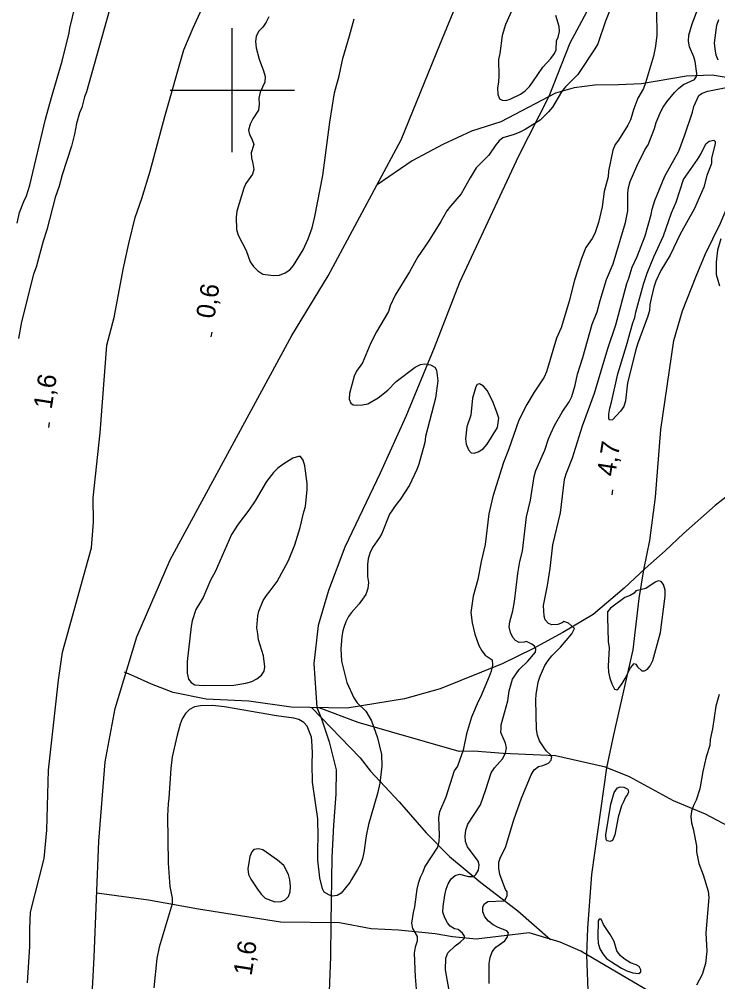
# Model space of a CAD drawing. Extents: x 282461 to 284471, y 5554090 to 5557646.
# Drawn here: x 282565.6 to 282678.3, y 5554656.3 to 5554811.4 of the extents above; entities that cross this region are included whole.
import ezdxf

# ---------------------------------------------------------------- set-up
doc = ezdxf.new("R2010")
doc.units = 0
for name, color, linetype in [('Niveau 1', 7, 'Continuous'), ('Niveau 2', 7, 'Continuous'), ('Niveau 22', 7, 'Continuous'), ('Niveau 3', 7, 'Continuous'), ('Niveau 4', 7, 'Continuous'), ('Niveau 61', 7, 'Continuous')]:
    doc.layers.add(name, color=color, linetype=linetype)

msp = doc.modelspace()

# ---------------------------------------------------------------- linework, layer by layer
at = {"layer": 'Niveau 1'}
for points in [[(282677.27, 5554788.31), (282677.22, 5554788.02), (282676.5, 5554786.22), (282676.01, 5554784.36), (282674.51, 5554780.92), (282672.21, 5554776.78), (282670.6, 5554773.4), (282669.08, 5554770.95), (282668.3, 5554769.2), (282667.97, 5554768.27), (282667.54, 5554766.41), (282667.33, 5554765.48), (282667.28, 5554764.5), (282667.01, 5554763.57), (282665.3, 5554759.09), (282665.03, 5554758.16), (282663.73, 5554752.82), (282663.38, 5554749.92), (282663.1, 5554749.05), (282662.6, 5554748.29), (282661.29, 5554746.88), (282660.83, 5554746.82), (282660.71, 5554747.1), (282660.7, 5554747.8), (282660.86, 5554748.78), (282661.13, 5554749.71), (282662.15, 5554754.3), (282663.57, 5554758.83), (282664.55, 5554762.49), (282664.88, 5554763.36), (282665.04, 5554764.23), (282666.29, 5554768.76), (282666.89, 5554770.51), (282667.95, 5554773.13), (282669.5, 5554776.5), (282670.83, 5554780.23), (282671.55, 5554781.97), (282672.76, 5554785.58), (282675.01, 5554788.85), (282675.51, 5554789.67), (282676.35, 5554791.36), (282676.86, 5554791.77), (282677.61, 5554791.96), (282677.85, 5554791.73), (282677.85, 5554791.33), (282677.26, 5554789.06), (282677.27, 5554788.31)], [(282660.51, 5554715.07), (282660.58, 5554711.14), (282660.77, 5554710.16), (282660.59, 5554707.21), (282660.66, 5554706.23), (282660.85, 5554705.25), (282661.16, 5554704.33), (282661.63, 5554703.47), (282661.98, 5554703.36), (282662.27, 5554703.6), (282662.83, 5554704.41), (282663.33, 5554705.23), (282664.17, 5554706.92), (282664.79, 5554707.62), (282665.08, 5554707.51), (282665.32, 5554707.11), (282666.03, 5554706.43), (282666.43, 5554706.44), (282666.94, 5554706.73), (282667.34, 5554707.26), (282667.79, 5554708.08), (282669.04, 5554712.61), (282669.8, 5554718.46), (282669.79, 5554719.44), (282669.54, 5554720.36), (282669.13, 5554720.82), (282668.66, 5554720.93), (282668.15, 5554720.74), (282666.67, 5554719.68), (282665.06, 5554719.31), (282664.77, 5554718.96), (282664.14, 5554718.6), (282663.28, 5554718.24), (282660.95, 5554716.52), (282660.5, 5554715.94), (282660.51, 5554715.07)], [(282663.04, 5554685.34), (282662.76, 5554684.7), (282662.22, 5554682.84), (282661.69, 5554680), (282661.3, 5554679.13), (282660.9, 5554678.95), (282660.38, 5554679.06), (282660.26, 5554679.34), (282660.24, 5554680.04), (282661.03, 5554684.96), (282661.57, 5554686.82), (282662.08, 5554687.58), (282662.54, 5554687.76), (282663.11, 5554687.71), (282663.75, 5554687.38), (282663.88, 5554686.97), (282663.71, 5554686.51), (282663.37, 5554686.1), (282663.04, 5554685.34)], [(282661.58, 5554662.83), (282660.92, 5554663.98), (282659.86, 5554665.58), (282659.44, 5554666.44), (282659.15, 5554666.44), (282658.98, 5554666.14), (282658.91, 5554663.54), (282658.98, 5554662.56), (282659.23, 5554661.64), (282659.71, 5554660.84), (282660.35, 5554660.1), (282661.11, 5554659.53), (282662.75, 5554658.52), (282663.62, 5554658.13), (282664.55, 5554657.79), (282665.53, 5554657.69), (282665.87, 5554657.93), (282665.87, 5554658.28), (282665.57, 5554658.79), (282665.1, 5554659.07), (282664.18, 5554659.41), (282663.36, 5554659.91), (282662.6, 5554660.54), (282662.01, 5554661.34), (282661.58, 5554662.83)]]:
    msp.add_lwpolyline(points, dxfattribs=at)
at = {"layer": 'Niveau 2'}
for points in [[(282673.61, 5554808.87), (282674.16, 5554810.68), (282675.82, 5554815.11)], [(282580.57, 5554814.3), (282576.48, 5554799.73), (282576.15, 5554798.91), (282575.72, 5554797.22), (282575.38, 5554796.35), (282574.89, 5554794.6), (282574.57, 5554792.91), (282574.09, 5554790.99), (282572.55, 5554786.33), (282572.06, 5554784.52), (282571.45, 5554782.71), (282570.09, 5554777.47), (282569.49, 5554775.67), (282568.35, 5554771.47), (282567.96, 5554770.36), (282566.01, 5554762.68), (282565.54, 5554760)], [(282578.7, 5554744.79), (282579.79, 5554758.9), (282580.93, 5554763.38), (282582.47, 5554771.35), (282583.33, 5554775.31), (282584.36, 5554779.5), (282585.4, 5554782.53), (282586.77, 5554786.96), (282589.11, 5554795.76), (282592.17, 5554806.48), (282593.67, 5554810.04), (282595.07, 5554813.08)], [(282661.24, 5554813.81), (282660.18, 5554811.12), (282658.91, 5554807.45), (282658.46, 5554806.63), (282655.7, 5554802.52), (282653.7, 5554800.52), (282653.08, 5554799.75), (282651.62, 5554797.23), (282650.99, 5554796.53), (282649.62, 5554795.17), (282647.22, 5554793.68), (282646.36, 5554793.21), (282645.44, 5554792.84), (282643.59, 5554792.29), (282643.02, 5554791.82), (282642.46, 5554791.17), (282641.33, 5554789.53), (282639.33, 5554787.46), (282638.32, 5554785.88), (282636.92, 5554783.31), (282635.15, 5554781.31), (282634.59, 5554780.54), (282633.63, 5554778.85), (282631.55, 5554775.56), (282629.91, 5554773.16), (282628.56, 5554770.7), (282626.25, 5554766.95), (282625.47, 5554765.26), (282625.2, 5554764.33), (282623.23, 5554761.05), (282622.33, 5554759.29), (282621, 5554756.08), (282620.04, 5554754.73)], [(282645.54, 5554813.89), (282644.02, 5554810.58), (282643.52, 5554808.78), (282643.15, 5554805.88), (282642.93, 5554804.95), (282642.97, 5554802.23), (282642.92, 5554801.31), (282642.76, 5554800.32), (282642.78, 5554799.34), (282643.07, 5554798.59), (282643.48, 5554798.36), (282644.12, 5554798.31), (282644.81, 5554798.54), (282646.47, 5554799.37), (282647.22, 5554799.9), (282647.9, 5554800.6), (282648.47, 5554801.35), (282650.06, 5554803.68), (282651.37, 5554805.08), (282651.94, 5554805.9), (282652.22, 5554806.48), (282652.26, 5554807.93)], [(282668.39, 5554812.72), (282668.45, 5554808.83), (282668.25, 5554807.09), (282667.88, 5554805.46), (282666.62, 5554801.15), (282666.29, 5554800.28), (282665.39, 5554798.7), (282664.72, 5554797.01), (282664.17, 5554795.2), (282663.78, 5554794.38), (282662.26, 5554791.92), (282661.7, 5554791.22), (282661.36, 5554790.34), (282660.67, 5554786.97), (282660.57, 5554786.04), (282659.97, 5554783.65), (282659.61, 5554781.21), (282659.02, 5554778.65), (282658.47, 5554776.91), (282658.02, 5554776.09), (282657, 5554774.62), (282656.28, 5554772.87), (282655.18, 5554769.38), (282654.32, 5554766), (282653.22, 5554762.39), (282653, 5554761.69), (282652.28, 5554760.06), (282650.63, 5554754.64), (282650.3, 5554753.77), (282648.66, 5554751.36), (282647.48, 5554749.37), (282646.2, 5554746.8), (282644.54, 5554742.02), (282643.71, 5554739.98), (282642.01, 5554734.51), (282641.36, 5554731.72), (282640.76, 5554726.78), (282640.11, 5554724.05), (282639.58, 5554721.14), (282638.82, 5554718.46), (282638.45, 5554715.85), (282638.66, 5554714.17), (282639.09, 5554712.33), (282639.76, 5554710.54), (282640.24, 5554709.68), (282640.77, 5554708.99), (282641.88, 5554708.2), (282641.96, 5554707.33), (282641.74, 5554706.4), (282641.41, 5554705.53), (282640.02, 5554702.2), (282639.63, 5554701.5), (282638.57, 5554698.99), (282637.75, 5554696.31), (282637.22, 5554693.64), (282636.28, 5554691.08), (282635.77, 5554690.31), (282634.4, 5554686.06), (282633.39, 5554683.73), (282633.24, 5554682.8), (282633.34, 5554679.91), (282633.3, 5554678.92), (282633.09, 5554678.05), (282631.06, 5554674.89), (282630.73, 5554674.01), (282630.28, 5554673.14), (282629.95, 5554672.2), (282629.73, 5554671.27), (282629.38, 5554668.43), (282629.16, 5554667.5), (282628.9, 5554665.76)], [(282652.26, 5554807.93), (282652.54, 5554808.51), (282652.76, 5554809.44), (282652.69, 5554810.25), (282652.15, 5554812.04)], [(282678.31, 5554804.85), (282678.01, 5554805.66), (282677.82, 5554806.64), (282677.74, 5554807.62), (282678.1, 5554810.46), (282678.43, 5554811.39)], [(282637.12, 5554664.16), (282636.42, 5554664.79), (282635.84, 5554664.89), (282635.14, 5554665.29), (282634.67, 5554665.86), (282634.25, 5554666.66), (282633.94, 5554667.58), (282633.99, 5554668.45), (282634.24, 5554670.31), (282634.46, 5554671.24), (282634.79, 5554672.11), (282635.3, 5554672.93), (282635.92, 5554673.46), (282636.61, 5554673.7), (282638.06, 5554673.32), (282638.93, 5554673.33), (282639.27, 5554673.63), (282639.67, 5554674.33), (282639.82, 5554675.2), (282639.64, 5554675.78), (282637.93, 5554678.07), (282637.62, 5554678.93), (282637.55, 5554679.8), (282637.65, 5554680.78), (282637.98, 5554681.71), (282640, 5554684.87), (282640.89, 5554687.32), (282641.71, 5554689.99), (282642.27, 5554690.81), (282643.58, 5554692.28), (282644.02, 5554693.16), (282644.18, 5554694.03), (282644.05, 5554694.78), (282643.27, 5554696.5), (282643.32, 5554697.2), (282643.37, 5554697.72), (282644.4, 5554701.61), (282644.66, 5554703.24), (282645.15, 5554705.1), (282646.22, 5554706.68), (282647.64, 5554707.98), (282648.89, 5554709.44), (282648.94, 5554709.91), (282648.7, 5554710.43), (282648.29, 5554710.71), (282647.42, 5554711.16), (282647.07, 5554711.04), (282646.26, 5554711.02), (282645.68, 5554711.3), (282645.21, 5554711.82), (282644.85, 5554712.62), (282644.66, 5554713.55), (282644.76, 5554714.36), (282645.25, 5554716.1), (282645.51, 5554717.61), (282646.01, 5554722.14), (282646.33, 5554724.05), (282646.76, 5554725.74), (282647.42, 5554731.25), (282648.07, 5554733.92), (282648.64, 5554737.75), (282648.91, 5554738.69), (282650.36, 5554742.01), (282650.96, 5554743.81), (282651.35, 5554744.69), (282651.96, 5554745.97), (282653.2, 5554748.14), (282654.33, 5554749.77), (282654.72, 5554750.65), (282655.26, 5554752.45), (282655.64, 5554754.25), (282656.52, 5554756.93), (282658.04, 5554762.29), (282658.82, 5554764.27), (282659.31, 5554766.13), (282660.35, 5554769.5), (282661.41, 5554772.01), (282663.37, 5554778.65), (282663.75, 5554780.56), (282663.75, 5554783.4), (282663.85, 5554784.33), (282664.13, 5554785.26), (282665.24, 5554787.77), (282666.53, 5554790.4), (282667.03, 5554791.21), (282668.09, 5554793.84), (282668.36, 5554794.77), (282669.02, 5554796.46), (282669.47, 5554797.28), (282670.04, 5554798.1), (282671.28, 5554799.62), (282671.97, 5554800.33), (282672.76, 5554800.92), (282674.49, 5554801.7), (282674.82, 5554802.17), (282674.87, 5554802.69), (282674.61, 5554804.6), (282674.42, 5554805.35), (282673.7, 5554806.96), (282673.57, 5554807.89), (282673.61, 5554808.87)], [(282644.39, 5554663.59), (282644.5, 5554664.23), (282644.26, 5554664.57), (282642.86, 5554665.07), (282642.05, 5554665.52), (282641.29, 5554666.09), (282640.7, 5554666.83), (282640.39, 5554667.63), (282640.38, 5554668.39), (282640.66, 5554668.91), (282641.17, 5554669.27), (282643.71, 5554669.36), (282644.06, 5554669.66), (282644.33, 5554670.24), (282644.32, 5554670.82), (282644.03, 5554671.22), (282643.12, 5554673.64), (282642.99, 5554674.62), (282642.97, 5554675.6), (282643.25, 5554676.41), (282644.03, 5554677.99), (282645.4, 5554682.46), (282646.61, 5554685.9), (282648.16, 5554689.68), (282648.67, 5554690.5), (282649.35, 5554691.03), (282650.04, 5554691.21), (282650.96, 5554691.58), (282651.41, 5554692.05), (282651.52, 5554692.57), (282651.28, 5554692.91), (282650.58, 5554693.54), (282649.51, 5554695.14), (282649.21, 5554696.06), (282649.02, 5554696.98), (282648.93, 5554701.78), (282648.98, 5554702.65), (282649.29, 5554704.62), (282649.62, 5554705.56), (282650.4, 5554707.3), (282650.91, 5554708.12), (282651.53, 5554708.88), (282652.89, 5554710.24), (282654.76, 5554712.41), (282655.15, 5554713.28), (282654.21, 5554714.13), (282653.45, 5554714.41), (282653.17, 5554714.17), (282652.48, 5554713.93), (282651.5, 5554713.86), (282650.98, 5554714.08), (282650.45, 5554714.65), (282650.26, 5554715.23), (282650.18, 5554716.96), (282650.81, 5554720.21), (282651.23, 5554722.94), (282651.68, 5554726.76), (282652.92, 5554731.87), (282653.53, 5554737.26), (282653.8, 5554738.2), (282654.85, 5554740.76), (282656.44, 5554745.93), (282658.37, 5554751.17), (282660.56, 5554758.38), (282661.82, 5554762.16), (282663.61, 5554768.85), (282663.95, 5554769.72), (282664.44, 5554771.47), (282665.27, 5554773.21), (282666.55, 5554776.53), (282667.53, 5554779.96), (282667.68, 5554780.83), (282668.12, 5554782.23), (282669.73, 5554786.13), (282671.97, 5554790.16), (282672.97, 5554792.78), (282674.18, 5554796.45), (282674.39, 5554797.38), (282675.23, 5554799.13), (282675.74, 5554799.49), (282676.66, 5554799.85), (282679.6, 5554800.42)], [(282678.74, 5554776.04), (282678.2, 5554774.23), (282678, 5554772.26), (282677.98, 5554770.29), (282678.53, 5554768.45)], [(282620.04, 5554754.73), (282619.65, 5554753.91), (282618.88, 5554751.12), (282618.84, 5554750.19), (282619.08, 5554749.55), (282619.49, 5554749.27), (282620.02, 5554749.22), (282621, 5554749.3), (282621.86, 5554749.48), (282623.53, 5554750.44), (282625.07, 5554751.68), (282626.43, 5554753.04), (282629.46, 5554755.35), (282630.32, 5554755.82), (282631.02, 5554755.89), (282631.95, 5554755.73), (282632.65, 5554755.34), (282632.94, 5554754.88), (282633.15, 5554753.14), (282632.73, 5554750.35), (282631.16, 5554744.18), (282631.06, 5554743.25), (282630.08, 5554739.76), (282629.75, 5554738.88), (282628.57, 5554736.37), (282627.05, 5554734.02), (282626.43, 5554733.26), (282625.35, 5554731.68), (282624.08, 5554728.58), (282623.74, 5554727.94), (282622.61, 5554726.3), (282622.16, 5554725.42), (282621.89, 5554724.49), (282621.79, 5554723.56), (282621.82, 5554721.65), (282621.95, 5554720.66), (282621.85, 5554719.68), (282621.52, 5554718.74), (282620.45, 5554717.22), (282619.2, 5554715.86), (282618.75, 5554715.22), (282618.3, 5554714.34), (282617.97, 5554713.41), (282617.8, 5554712.88), (282617.65, 5554711.95), (282617.51, 5554709.98), (282617.6, 5554708.01), (282618.47, 5554704.55), (282619.61, 5554702.07), (282620.15, 5554701.27), (282621.5, 5554699.95), (282622.45, 5554698.4), (282623.43, 5554695.64), (282624.05, 5554692.98), (282624.08, 5554691.07), (282623.78, 5554688.34), (282623.41, 5554686.65), (282621.93, 5554681.7), (282621.56, 5554679.84), (282621.2, 5554677.16), (282620.98, 5554676.23), (282620.65, 5554675.3), (282620.2, 5554674.42), (282619.19, 5554672.84), (282618.96, 5554672.32), (282617.55, 5554670.61), (282616.92, 5554670.25), (282616.17, 5554670.13), (282615.64, 5554670.29), (282614.82, 5554670.8), (282614.52, 5554671.32), (282614.09, 5554673.11), (282613.81, 5554675.95), (282613.78, 5554677.8), (282613.86, 5554679.66), (282613.81, 5554682.61), (282612.9, 5554688.51), (282612.85, 5554691.41), (282612.93, 5554693.27), (282612.84, 5554695.18), (282612.77, 5554695.76), (282612.05, 5554697.54), (282611.52, 5554698.11), (282610.7, 5554698.62), (282609.94, 5554698.79), (282607.1, 5554699.2), (282598.74, 5554700.64), (282596.83, 5554700.84), (282594.86, 5554700.81), (282593.88, 5554700.62), (282593.07, 5554700.2), (282592.45, 5554699.55), (282591.94, 5554698.73), (282591.61, 5554697.86), (282591.12, 5554696.05), (282590.31, 5554692.56), (282590.11, 5554690.7), (282589.79, 5554685.94), (282589.63, 5554685.01), (282589.55, 5554683.1), (282589.68, 5554675.45)], [(282642.95, 5554747.16), (282642.65, 5554748.14), (282641.92, 5554749.92), (282641.08, 5554751.59), (282640.49, 5554752.33), (282639.85, 5554752.67), (282639.5, 5554752.55), (282639.28, 5554752.2), (282638.73, 5554750.39), (282638.43, 5554747.61), (282637.83, 5554745.74), (282637.57, 5554743.83), (282637.7, 5554742.96), (282638.06, 5554742.04), (282638.53, 5554741.58), (282639, 5554741.53), (282639.63, 5554741.71), (282640.43, 5554742.19), (282641.06, 5554742.95), (282642.75, 5554745.65), (282642.95, 5554747.16)], [(282566.98, 5554656.19), (282567.35, 5554662.05), (282567.35, 5554664.89), (282567.48, 5554667.56), (282569.65, 5554676.23), (282570.09, 5554680.76), (282570.38, 5554690.45), (282571.99, 5554704.91), (282572.6, 5554709.44), (282577.29, 5554726.27), (282577.62, 5554730.39), (282577.55, 5554734.33), (282578.7, 5554744.79)], [(282595.31, 5554718.27), (282594.13, 5554716.33), (282593.52, 5554714.47), (282593.36, 5554713.6), (282592.71, 5554707.96), (282592.74, 5554706.05), (282592.93, 5554705.12), (282593.35, 5554704.55), (282593.93, 5554704.21), (282594.63, 5554704.11), (282595.55, 5554704.06), (282600.24, 5554704.14), (282602.2, 5554704.46), (282603.13, 5554704.71), (282603.93, 5554705.13), (282604.73, 5554705.72), (282605.12, 5554706.36), (282605.23, 5554707.06), (282605.02, 5554708.85), (282604.23, 5554711.45), (282604.09, 5554712.38), (282603.96, 5554713.36), (282604.1, 5554715.28), (282604.26, 5554716.03), (282604.98, 5554717.78), (282605.49, 5554718.6), (282606.12, 5554719.31), (282607.25, 5554720.83), (282609.04, 5554724.23), (282610.1, 5554726.74), (282610.92, 5554729.53), (282611.51, 5554732.04), (282611.79, 5554732.91), (282612.09, 5554735.64), (282612.07, 5554736.63), (282611.67, 5554739.46), (282611.43, 5554740.38), (282611.01, 5554740.96), (282610.66, 5554740.95), (282609.74, 5554740.71), (282608.14, 5554739.69), (282607.34, 5554739.1), (282606.66, 5554738.39), (282605.52, 5554736.93), (282603.67, 5554733.82), (282602.65, 5554732.3), (282600.95, 5554730.07), (282599.88, 5554728.43), (282597.21, 5554722.41), (282596.48, 5554721.07), (282595.31, 5554718.27)], [(282678.5, 5554702.6), (282677.95, 5554700.74), (282677.44, 5554697.09), (282677.06, 5554695.35), (282676.96, 5554694.42), (282676.41, 5554692.56), (282675.88, 5554690.24), (282675.4, 5554687.45), (282674.8, 5554685.59), (282674.35, 5554684.72), (282674.02, 5554683.84), (282673.92, 5554682.92), (282674.05, 5554681.93), (282674.3, 5554681.01), (282674.81, 5554678.24), (282674.83, 5554677.26), (282675.21, 5554675.42), (282675.93, 5554673.58), (282676.73, 5554670.93), (282676.8, 5554669.94), (282676.32, 5554664.21), (282676.49, 5554661.26), (282676.29, 5554659.29), (282675.74, 5554657.49), (282674.85, 5554655.8)], [(282608.33, 5554675.05), (282607.27, 5554675.96), (282604.93, 5554677.6), (282604.23, 5554677.76), (282603.48, 5554677.64), (282603.14, 5554677.28), (282602.81, 5554676.53), (282602.49, 5554674.55), (282602.63, 5554673.63), (282602.99, 5554672.88), (282604.05, 5554671.27), (282604.65, 5554670.47), (282605.29, 5554669.79), (282606.87, 5554669.23), (282607.85, 5554669.25), (282608.54, 5554669.55), (282609.05, 5554670.08), (282609.32, 5554670.84), (282609.37, 5554671.76), (282609.29, 5554672.75), (282609.05, 5554673.61), (282608.33, 5554675.05)], [(282589.68, 5554675.45), (282589.92, 5554671.68), (282590.3, 5554669.83), (282590.32, 5554668.91), (282588.18, 5554661.92), (282587.81, 5554660.11), (282587.37, 5554655.35)], [(282628.9, 5554665.76), (282629.03, 5554664.95), (282629.81, 5554663.63), (282629.82, 5554662.88), (282629.49, 5554661.94), (282629.33, 5554660.96), (282629.46, 5554657.13), (282629.66, 5554655.23)], [(282635.1, 5554654), (282634.39, 5554658.27), (282634.42, 5554660.12), (282634.75, 5554661), (282635.94, 5554662.12), (282636.74, 5554662.71), (282637.43, 5554663.35), (282637.42, 5554663.7), (282637.12, 5554664.16)], [(282641.4, 5554656.08), (282641.4, 5554659.26), (282641.56, 5554660.25), (282641.89, 5554661.18), (282642.46, 5554661.94), (282643.94, 5554662.95), (282644.39, 5554663.59)]]:
    msp.add_lwpolyline(points, dxfattribs=at)
at = {"layer": 'Niveau 22'}
for points in [[(282576.87, 5554644.06), (282577.75, 5554660.31), (282578.47, 5554678.99), (282579.52, 5554691.76), (282581.11, 5554700.37), (282584.63, 5554711.92), (282589.97, 5554724.3), (282609.59, 5554760.45), (282615.45, 5554770.07), (282627.24, 5554791.97), (282633.46, 5554807.28), (282646.59, 5554839.15), (282652.58, 5554854.81), (282658.74, 5554867.21), (282663.98, 5554879.49), (282672.18, 5554899.48)], [(282658.58, 5554815.43), (282654.43, 5554807.58), (282651.03, 5554798.97), (282646.15, 5554789.34), (282636.65, 5554769), (282632.55, 5554758.5), (282627.99, 5554747.41), (282623.86, 5554738.29), (282618.16, 5554726.37), (282615.5, 5554719.37), (282613.86, 5554713.77), (282613.16, 5554707.62), (282613.62, 5554700.51), (282614.33, 5554698.88), (282615.6, 5554695.01), (282616.72, 5554690.51), (282616.67, 5554686.57), (282616.29, 5554681.57), (282616.04, 5554676.35), (282615.86, 5554665.85), (282615.85, 5554660.36), (282615.53, 5554652.01)], [(282657.45, 5554653.51), (282657.13, 5554660.69), (282657.3, 5554664.96), (282657.95, 5554673.65), (282660.39, 5554690.83), (282661.49, 5554696.14), (282664.6, 5554709.84), (282665.61, 5554718.07), (282666.34, 5554722.71), (282667.32, 5554727.46), (282668.24, 5554734.41), (282669.1, 5554745.3), (282671.16, 5554759.68), (282672.58, 5554764.44), (282674.8, 5554770.04), (282676.24, 5554773.53), (282678.7, 5554778.55), (282681.71, 5554785.66), (282682.91, 5554789.73), (282684.09, 5554794.72), (282685.66, 5554800.53), (282686.94, 5554802.85), (282688.49, 5554806.81), (282689.99, 5554813.67)], [(282741.69, 5554794.44), (282734.73, 5554793.27), (282727.71, 5554792.24), (282722.27, 5554792.38), (282708.4, 5554794.35), (282703.85, 5554795.66), (282696.49, 5554797.47), (282687.75, 5554799.84), (282681.87, 5554801.65), (282677.37, 5554802.41), (282673.21, 5554802.24), (282665.97, 5554801), (282662.27, 5554800.84), (282658.46, 5554800.78), (282655.11, 5554800.39), (282652.11, 5554799.53), (282643.27, 5554794.87), (282638.55, 5554793.4), (282633.95, 5554791.25), (282629.01, 5554788.62), (282623.35, 5554784.76)], [(282682.78, 5554736.95), (282677.86, 5554733.06), (282672.73, 5554728.58), (282669.77, 5554725.76), (282666.58, 5554722.94), (282663.17, 5554719.76), (282658.17, 5554715.51), (282653.26, 5554712.63), (282648.45, 5554709.98), (282643.52, 5554707.57), (282633.52, 5554703.55), (282627.76, 5554701.94), (282618.52, 5554700.4), (282609.48, 5554700.6), (282602.64, 5554701.54), (282595.8, 5554701.89), (282590.46, 5554702.97), (282586.96, 5554704.3)], [(282586.96, 5554704.3), (282584.1, 5554705.56), (282582.63, 5554706.21)], [(282612.75, 5554700.53), (282620.62, 5554692.43), (282622.28, 5554690.25), (282626.88, 5554685.35), (282631.26, 5554680.35), (282635.03, 5554676.51), (282640.08, 5554672.34), (282646.05, 5554667.76), (282651.3, 5554663.16)], [(282739.94, 5554663.66), (282732.82, 5554664.42), (282728.56, 5554665.35), (282722.44, 5554667.19), (282715.63, 5554669.91), (282712.24, 5554670.73), (282705.43, 5554673.07), (282697.28, 5554675.51), (282685.98, 5554678.62), (282680.96, 5554680.87), (282676.28, 5554683.36), (282671.15, 5554685.51), (282664.03, 5554689.35), (282660.19, 5554690.91), (282652.08, 5554692.72), (282643.64, 5554693.12), (282638.89, 5554693.47), (282636.58, 5554693.42), (282620.28, 5554698.1), (282614, 5554700.5)], [(282667.41, 5554654.67), (282656.2, 5554661.25), (282652.83, 5554662.7), (282647.84, 5554664.22), (282639.31, 5554663.2), (282635.48, 5554663.57), (282632.7, 5554664.08), (282626.78, 5554664.65), (282622.37, 5554664.89), (282617.26, 5554665.83), (282607.77, 5554665.92), (282594.55, 5554668.04), (282586.5, 5554669.49), (282578.15, 5554670.63)]]:
    msp.add_lwpolyline(points, dxfattribs=at)
at = {"layer": 'Niveau 3'}
for p, q in [((282596.61, 5554760.23), (282596.73, 5554761.02)), ((282570.39, 5554745.66), (282570.51, 5554746.45)), ((282661.22, 5554734.81), (282661.34, 5554735.6))]:
    msp.add_line(p, q, dxfattribs=at)
at = {"layer": 'Niveau 4'}
for points in [[(282565.33, 5554778.57), (282565.7, 5554780.26), (282566.37, 5554782.07), (282566.81, 5554782.95), (282567.36, 5554784.7), (282569.9, 5554795.3), (282570.83, 5554798.8), (282572.58, 5554804.68), (282573.71, 5554809.23), (282573.82, 5554809.99), (282574.68, 5554813.54)], [(282605.86, 5554811.83), (282605.47, 5554810.95), (282604.9, 5554810.14), (282604.21, 5554809.44), (282603.82, 5554808.62), (282603.71, 5554807.81), (282603.84, 5554806.83), (282604.33, 5554804.98), (282605.05, 5554803.13), (282605.29, 5554802.21), (282605.24, 5554801.28), (282604.51, 5554799.65), (282604.29, 5554798.72), (282604.31, 5554797.74), (282604.2, 5554796.76), (282603.3, 5554795.36), (282602.9, 5554794.49), (282602.62, 5554793.56), (282602.75, 5554792.86), (282603.16, 5554792.17), (282603.46, 5554791.25), (282603.02, 5554789.91), (282603.09, 5554789.1), (282603.33, 5554788.18), (282603.46, 5554787.19), (282603.24, 5554786.44), (282602.16, 5554784.98), (282601.88, 5554784.23), (282600.71, 5554780.51), (282600.61, 5554779.53), (282600.69, 5554777.56), (282600.93, 5554776.63), (282602.24, 5554774.15), (282602.89, 5554772.36), (282603.43, 5554771.56), (282604.13, 5554770.87), (282604.94, 5554770.36), (282606.62, 5554770.14), (282607.6, 5554770.2), (282608.52, 5554770.56), (282609.27, 5554771.03), (282609.84, 5554771.73), (282611.43, 5554774.29), (282612.21, 5554776.03), (282612.88, 5554777.83), (282613.32, 5554779.63), (282614.57, 5554786.24), (282615.73, 5554794.83), (282616.48, 5554799.58), (282617.2, 5554802.31), (282617.8, 5554805.09), (282618.91, 5554808.75), (282619.62, 5554811.48)]]:
    msp.add_lwpolyline(points, dxfattribs=at)
at = {"layer": 'Niveau 61'}
for points in [[(282600, 5554790), (282600, 5554810)], [(282590, 5554800), (282610, 5554800)]]:
    msp.add_lwpolyline(points, dxfattribs=at)

# ---------------------------------------------------------------- texts
at = {"layer": 'Niveau 3'}
for s, p in [('0,6  ', (282597.09, 5554763.07)), ('1,6  ', (282570.87, 5554748.5)), ('4,7  ', (282661.7, 5554737.65)), ('1,6  ', (282603.1, 5554657.22))]:
    msp.add_text(s, height=3, rotation=81.0957, dxfattribs=at).set_placement(p)

doc.saveas('drawing.dxf')
